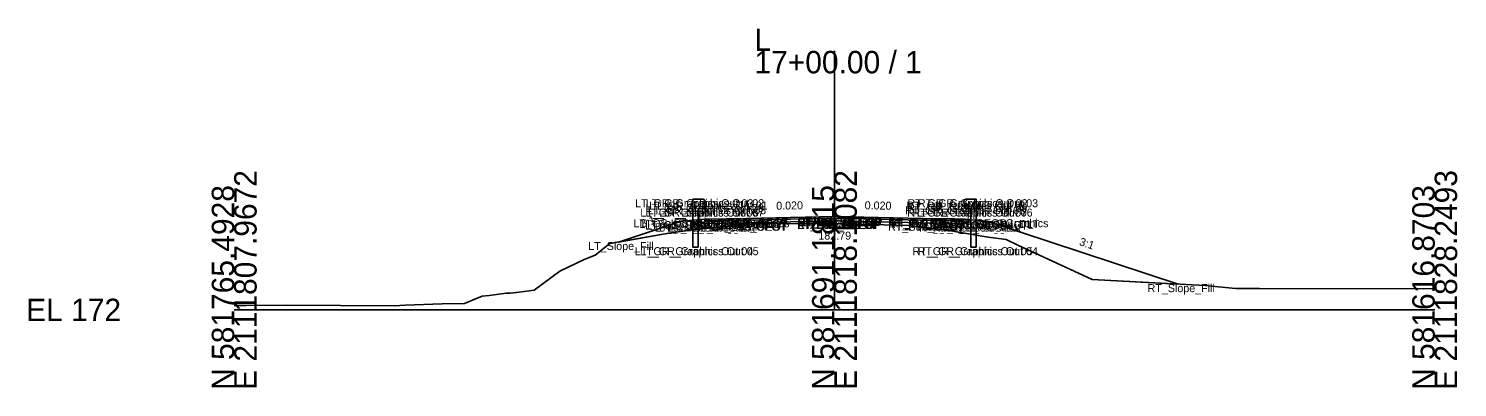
# Model space of a CAD drawing. Extents: x -486 to 1153, y -333 to 9539.
# Drawn here: x -25.7 to 152.8, y 7490.3 to 7535.2 of the extents above; entities that cross this region are included whole.
import ezdxf

# ---------------------------------------------------------------- set-up
doc = ezdxf.new("R2010")
doc.units = 0
for name, color, linetype in [('Default', 7, 'Continuous'), ('Exist Cross Section Cell', 7, 'Continuous'), ('Exist XS Ground Line', 7, 'Continuous'), ('Prop CMT Guardrail Graphics', 7, 'Continuous'), ('Prop CMT Pvmt Course 1', 7, 'Continuous'), ('Prop CMT Pvmt Course 2', 7, 'Continuous'), ('Prop CMT Pvmt Course 3', 7, 'Continuous'), ('Prop CMT Pvmt Surface', 7, 'Continuous'), ('Prop CMT Pvmt Surface Shoulder', 7, 'Continuous'), ('Prop CMT Shld Paved Course 1', 7, 'Continuous'), ('Prop CMT Shld Paved Course 2', 7, 'Continuous'), ('Prop CMT Shld Paved Course 3', 7, 'Continuous'), ('Prop CMT Slope Grass', 7, 'Continuous'), ('Prop CMT Subgrade Earthwork', 7, 'Continuous'), ('Prop XS Earthwork Shape', 7, 'Continuous'), ('Prop XS SE Text', 7, 'Continuous'), ('Prop XS Side Slope Text', 7, 'Continuous'), ('Scratch_Level_0', 7, 'Continuous')]:
    doc.layers.add(name, color=color, linetype=linetype)

msp = doc.modelspace()

# ---------------------------------------------------------------- linework, layer by layer
at = {"layer": 'Exist Cross Section Cell'}
for p, q in [((75, 7500), (75, 7532.38)), ((0, 7500), (75, 7500)), ((75, 7500), (150, 7500))]:
    msp.add_line(p, q, dxfattribs=at)
at = {"layer": 'Exist XS Ground Line'}
for p, q in [((46.92, 7508.3), (54.29, 7509.61)), ((54.29, 7509.61), (57.27, 7510.01)), ((57.27, 7510.01), (65.13, 7510.75)), ((65.13, 7510.75), (66.97, 7510.76)), ((66.97, 7510.76), (74.65, 7510.79)), ((74.65, 7510.79), (75, 7510.79)), ((75, 7510.79), (76.59, 7510.75)), ((76.59, 7510.75), (84.26, 7510.57)), ((84.26, 7510.57), (88.54, 7510.04)), ((88.54, 7510.04), (94.19, 7509.1)), ((94.19, 7509.1), (96.46, 7508.79)), ((45.09, 7506.86), (46.92, 7508.3)), ((96.46, 7508.79), (97.93, 7508.09)), ((97.93, 7508.09), (107.19, 7503.82)), ((40.68, 7504.84), (43.72, 7506.32)), ((43.72, 7506.32), (45.09, 7506.86)), ((37.47, 7502.46), (40.68, 7504.84)), ((107.19, 7503.82), (121.3, 7503.04)), ((31.86, 7501.81), (33.98, 7502.08)), ((33.98, 7502.08), (34.51, 7502.08)), ((34.51, 7502.08), (35.59, 7502.2)), ((35.59, 7502.2), (37.47, 7502.46)), ((121.3, 7503.04), (125.11, 7502.69)), ((125.11, 7502.69), (128.12, 7502.66)), ((128.12, 7502.66), (148.57, 7502.65)), ((148.57, 7502.65), (150, 7502.66)), ((0, 7500.55), (0.84, 7500.54)), ((0.84, 7500.54), (1.51, 7500.56)), ((1.51, 7500.56), (6.52, 7500.61)), ((6.52, 7500.61), (20.03, 7500.51)), ((20.03, 7500.51), (21.37, 7500.59)), ((21.37, 7500.59), (25.97, 7500.76)), ((25.97, 7500.76), (28.77, 7500.82)), ((28.77, 7500.82), (30.05, 7501.34)), ((30.05, 7501.34), (30.98, 7501.74)), ((30.98, 7501.74), (31.86, 7501.81))]:
    msp.add_line(p, q, dxfattribs=at)
at = {"layer": 'Prop CMT Guardrail Graphics'}
for points in [[(57.3, 7507.84), (57.3, 7513.84)], [(57.3, 7513.84), (58.63, 7513.84), (58.9, 7513.54)], [(58.9, 7512.96), (58.63, 7512.67), (57.96, 7512.67)], [(57.96, 7512.67), (57.96, 7507.84)], [(58.9, 7513.54), (58.63, 7513.25)], [(58.63, 7513.25), (58.9, 7512.96)], [(92.7, 7513.84), (91.37, 7513.84), (91.1, 7513.54)], [(91.1, 7513.54), (91.37, 7513.25)], [(91.37, 7513.25), (91.1, 7512.96)], [(91.1, 7512.96), (91.37, 7512.67), (92.04, 7512.67)], [(92.04, 7512.67), (92.04, 7507.84)], [(92.7, 7507.84), (92.7, 7513.84)], [(57.96, 7507.84), (57.3, 7507.84)], [(92.04, 7507.84), (92.7, 7507.84)]]:
    msp.add_lwpolyline(points, dxfattribs=at)
at = {"layer": 'Prop CMT Pvmt Course 1'}
for points in [[(75, 7511.66), (64, 7511.44)], [(64, 7511.24), (75, 7511.46)], [(64, 7511.44), (64, 7511.24)], [(75, 7511.46), (75, 7511.66)], [(75, 7511.66), (86, 7511.44)], [(75, 7511.46), (75, 7511.66)], [(86, 7511.24), (75, 7511.46)], [(86, 7511.44), (86, 7511.24)]]:
    msp.add_lwpolyline(points, dxfattribs=at)
msp.add_lwpolyline([(75, 7511.46), (75, 7511.54), (75, 7511.54), (75, 7511.46)], close=True, dxfattribs=at)
msp.add_lwpolyline([(75, 7511.46), (75, 7511.54), (75, 7511.54), (75, 7511.46)], close=True, dxfattribs=at)
at = {"layer": 'Prop CMT Pvmt Course 2'}
for points in [[(75, 7511.46), (64, 7511.24)], [(64, 7511.24), (64, 7510.9)], [(64, 7510.9), (75, 7511.12)], [(75, 7511.12), (75, 7511.46)], [(75, 7511.12), (75, 7511.46)], [(75, 7511.46), (86, 7511.24)], [(86, 7510.9), (75, 7511.12)], [(86, 7511.24), (86, 7510.9)]]:
    msp.add_lwpolyline(points, dxfattribs=at)
at = {"layer": 'Prop CMT Pvmt Course 3'}
for points in [[(75, 7511.12), (64, 7510.9)], [(64, 7510.9), (64, 7510.9)], [(75, 7511.12), (75, 7511.12)], [(75, 7511.12), (86, 7510.9)], [(75, 7511.12), (75, 7511.12)], [(86, 7510.9), (86, 7510.9)]]:
    msp.add_lwpolyline(points, dxfattribs=at)
at = {"layer": 'Prop CMT Pvmt Surface'}
for points in [[(75, 7511.66), (64, 7511.44)], [(75, 7511.66), (86, 7511.44)]]:
    msp.add_lwpolyline(points, dxfattribs=at)
at = {"layer": 'Prop CMT Pvmt Surface Shoulder'}
for points in [[(64, 7511.44), (59, 7511.34)], [(86, 7511.44), (91, 7511.34)]]:
    msp.add_lwpolyline(points, dxfattribs=at)
at = {"layer": 'Prop CMT Shld Paved Course 1'}
for points in [[(64, 7511.44), (59, 7511.34), (58.79, 7511.13)], [(58.79, 7511.13), (64, 7511.24)], [(64, 7511.24), (64, 7511.44)], [(86, 7511.44), (91, 7511.34), (91.21, 7511.13)], [(86, 7511.24), (86, 7511.44)], [(91.21, 7511.13), (86, 7511.24)]]:
    msp.add_lwpolyline(points, dxfattribs=at)
at = {"layer": 'Prop CMT Shld Paved Course 2'}
for points in [[(64, 7511.24), (58.79, 7511.13), (58.45, 7510.79)], [(58.45, 7510.79), (64, 7510.9)], [(64, 7510.9), (64, 7511.24)], [(86, 7511.24), (91.21, 7511.13), (91.55, 7510.79)], [(86, 7510.9), (86, 7511.24)], [(91.55, 7510.79), (86, 7510.9)]]:
    msp.add_lwpolyline(points, dxfattribs=at)
at = {"layer": 'Prop CMT Shld Paved Course 3'}
for points in [[(64, 7510.9), (58.45, 7510.79)], [(64, 7510.9), (64, 7510.9)], [(86, 7510.9), (91.55, 7510.79)], [(86, 7510.9), (86, 7510.9)], [(58.45, 7510.79), (58.45, 7510.79), (58.45, 7510.79)], [(91.55, 7510.79), (91.55, 7510.79), (91.55, 7510.79)]]:
    msp.add_lwpolyline(points, dxfattribs=at)
at = {"layer": 'Prop CMT Slope Grass'}
for points in [[(55.9, 7511.1), (48, 7508.49)], [(58.9, 7511.34), (55.9, 7511.1)], [(59, 7511.34), (58.9, 7511.34)], [(91, 7511.34), (91.1, 7511.34)], [(91.1, 7511.34), (94.1, 7511.1)], [(94.1, 7511.1), (117.95, 7503.22)]]:
    msp.add_lwpolyline(points, dxfattribs=at)
at = {"layer": 'Prop CMT Subgrade Earthwork'}
for points in [[(58.45, 7510.79), (57.98, 7511.26)], [(64, 7510.9), (58.45, 7510.79)], [(75, 7511.12), (64, 7510.9)], [(75, 7511.12), (86, 7510.9)], [(86, 7510.9), (91.55, 7510.79)], [(91.55, 7510.79), (92.02, 7511.26)]]:
    msp.add_lwpolyline(points, dxfattribs=at)
at = {"layer": 'Prop XS Earthwork Shape'}
msp.add_lwpolyline([(76.59, 7510.75), (84.26, 7510.57), (88.54, 7510.04), (94.19, 7509.1), (96.46, 7508.79), (97.93, 7508.09), (107.19, 7503.82), (117.95, 7503.22), (94.1, 7511.1), (92.02, 7511.26), (91.55, 7510.79), (86, 7510.9), (75, 7511.12), (64, 7510.9), (58.45, 7510.79), (57.98, 7511.26), (55.9, 7511.1), (48, 7508.49), (54.29, 7509.61), (57.27, 7510.01), (65.13, 7510.75), (66.97, 7510.76), (74.65, 7510.79), (75, 7510.79)], close=True, dxfattribs=at)

# ---------------------------------------------------------------- texts
at = {"layer": 'Default'}
for s, height, p in [('182.79', 1, (72.99, 7508.79)), ('-', 0.0001, (0, 7500))]:
    msp.add_text(s, height=height, dxfattribs=at).set_placement(p)
at = {"layer": 'Exist Cross Section Cell'}
for s, p in [('L', (65, 7532.38)), ('17+00.00 / 1', (65, 7529.58)), ('EL 172', (-26, 7498.6))]:
    msp.add_text(s, height=2.8, dxfattribs=at).set_placement(p)
for s, p in [('E 2111807.9672', (2.8, 7490)), ('E 2111818.1082', (77.8, 7490)), ('E 2111828.2493', (152.8, 7490)), ('N 581765.4928', (0, 7490)), ('N 581691.1815', (75, 7490)), ('N 581616.8703', (150, 7490))]:
    msp.add_text(s, height=2.8, rotation=90, dxfattribs=at).set_placement(p)
at = {"layer": 'Prop XS SE Text'}
for rotation, p in [(1.1458, (67.73, 7512.52)), (358.8542, (78.77, 7512.59))]:
    msp.add_text('0.020', height=1, rotation=rotation, dxfattribs=at).set_placement(p)
at = {"layer": 'Prop XS Side Slope Text'}
for rotation, p in [(18.2629, (50.96, 7510.26)), (341.7371, (105.51, 7508.12))]:
    msp.add_text('3:1', height=1, rotation=rotation, dxfattribs=at).set_placement(p)
at = {"layer": 'Scratch_Level_0'}
for s, p in [('LT_GR_Graphics Out 03', (50.08, 7512.84)), ('LT_GR_Graphics Out 06', (50.74, 7511.67)), ('LT_GR_Graphics Out 07', (51.39, 7511.67)), ('LT_GR_Graphics Out 09', (51.4, 7512.25)), ('LT_GR_Graphics Out 02', (51.43, 7512.84)), ('LT_GR_Graphics Out 08', (51.67, 7511.96)), ('LT_GR_Graphics Out 01', (51.85, 7512.54)), ('RT_GR_Graphics Out 08', (83.81, 7511.96)), ('RT_GR_Graphics Out 01', (83.99, 7512.54)), ('RT_GR_Graphics Out 07', (84.07, 7511.67)), ('RT_GR_Graphics Out 09', (84.09, 7512.25)), ('RT_GR_Graphics Out 02', (84.11, 7512.84)), ('RT_GR_Graphics Out 06', (84.75, 7511.67)), ('RT_GR_Graphics Out 03', (85.43, 7512.84)), ('LT_GS_OS_GR_Face_Graphics', (49.9, 7510.34)), ('LT_Sub_Trench_Out_DLT', (50.63, 7510.26)), ('LT_GS_OS_CTL', (51.36, 7510.1)), ('LT_PS2_OEOP', (54.57, 7510.13)), ('LT_PS1_OEOP', (54.91, 7510.34)), ('LT_PV2_OEOT', (59.75, 7510.24)), ('LT_PV3_OEOT', (59.75, 7509.9)), ('LT_Sub_OEOT', (59.77, 7509.9)), ('LT_PV1_OEOT', (59.87, 7510.44)), ('RT_PV2_OEEOP', (70.33, 7510.46)), ('RT_PV3_OEEOP', (70.33, 7510.12)), ('RT_Sub_OEEOP', (70.36, 7510.12)), ('LT_PV2_OEEOP', (70.39, 7510.46)), ('LT_PV3_OEEOP', (70.39, 7510.12)), ('LT_Sub_OEEOP', (70.42, 7510.12)), ('RT_PV1_OEEOP', (70.45, 7510.54)), ('LT_PV1_OEEOP', (70.51, 7510.54)), ('RT_PV2_IEEOP', (70.71, 7510.46)), ('LT_PV2_IEEOP', (70.77, 7510.46)), ('RT_PV1_IEEOP', (70.83, 7510.54)), ('LT_PV1_IEEOP', (70.89, 7510.54)), ('PV2_PGL', (72.35, 7510.46)), ('PV1_PGL', (72.47, 7510.66)), ('RT_PV2_OEOT', (81.69, 7510.24)), ('RT_PV3_OEOT', (81.69, 7509.9)), ('RT_Sub_OEOT', (81.71, 7509.9)), ('RT_PV1_OEOT', (81.81, 7510.44)), ('RT_GS_OS_GR_Face_Graphics', (82.04, 7510.34)), ('RT_Sub_Trench_Out_DLT', (84.61, 7510.26)), ('RT_PS1_OEOP', (86.85, 7510.34)), ('RT_PS2_OEOP', (86.94, 7510.13)), ('RT_GS_OS_CTL', (89.5, 7510.1)), ('LT_Sub_Trench_Out', (52.56, 7509.79)), ('LT_PS3_Shelf_Out', (53.1, 7509.79)), ('LT_PS3_OEOP', (54.23, 7509.79)), ('RT_Sub_Trench_Out', (85.6, 7509.79)), ('RT_PS3_Shelf_Out', (86.15, 7509.79)), ('RT_PS3_OEOP', (87.28, 7509.79)), ('LT_Slope_Fill', (44.24, 7507.49)), ('LT_GR_Graphics Out 04', (50.07, 7506.84)), ('LT_GR_Graphics Out 05', (50.74, 7506.84)), ('RT_GR_Graphics Out 05', (84.76, 7506.84)), ('RT_GR_Graphics Out 04', (85.41, 7506.84)), ('RT_Slope_Fill', (114.13, 7502.22))]:
    msp.add_text(s, height=1, dxfattribs=at).set_placement(p)

doc.saveas('drawing.dxf')
